// Mitsubishi GX Works2 project: 9.星三角启动   PLC: FX3U/FX3UC

PROGRAM MAIN
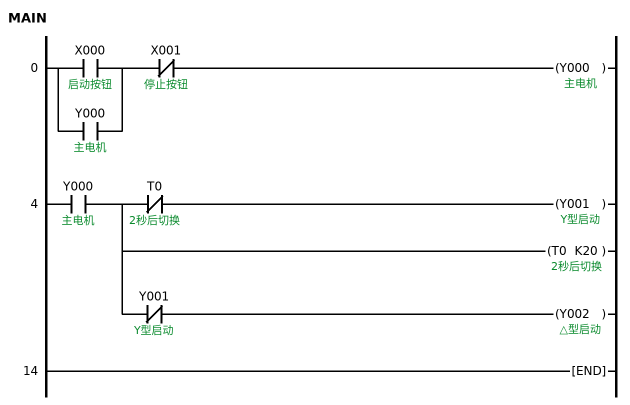
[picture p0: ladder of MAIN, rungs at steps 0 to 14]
0     LD      X000  ; 启动按钮
      OR      Y000  ; 主电机
      ANI     X001  ; 停止按钮
      OUT     Y000  ; 主电机
4     LD      Y000  ; 主电机
      MPS
      ANI     T0  ; 2秒后切换
      OUT     Y001  ; Y型启动
      MPP
      OUT     T0 K20  ; 2秒后切换
      ANI     Y001  ; Y型启动
      OUT     Y002  ; △型启动
14    END
END_PROGRAM
